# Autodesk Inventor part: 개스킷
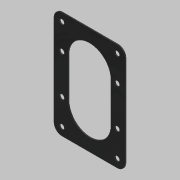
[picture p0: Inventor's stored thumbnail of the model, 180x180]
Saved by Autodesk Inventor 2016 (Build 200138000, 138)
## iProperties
Created: 2019-03
Part Number: 개스킷
Material: 고무
Document SubType Name: Modeling
Designer: mduedu
Density: 1 g/cm^3
Appearance: 고무 - 검은색 - 버전 1.1
Author: mduedu
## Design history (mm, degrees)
sketch "스케치1"
  geometry: L1 (-60, 40)-(60, 40); L2 (60, 40)-(60, -40); L3 (60, -40)-(-60, -40); L4 (-60, -40)-(-60, 40); L5 (-60, 40)-(60, -40); L6 (60, 40)-(-60, -40); 1 further point
  constraints: 12 end point, 2 midpoint, 2 parallel, 1 horizontal, 1 perpendicular
  dimensions: "d21" = 120 distance of L2.end L3.end; "d22" = 80 distance of L1.end L2.end
extrude "돌출1" new body sketch "스케치1" distance "d3" = 1; taper "d4" = 0 deg
fillet "모깎기1" dims "d5" = 9
sketch "스케치2" dims "d6" = 48
  geometry: L1 (-24, -22)-(24, -22); L2 (24, -22)-(24, 22); L3 (24, 22)-(-24, 22); L4 (-24, 22)-(-24, -22); L5 (-24, -22)-(24, 22); L6 (24, -22)-(-24, 22); 3 further points
  constraints: 12 end point, 4 midpoint, 2 horizontal alignment, 2 parallel, 1 horizontal, 1 perpendicular, 4 other
  dimensions: "d8" = 22 distance from line of L3 point (0, 0)
extrude "돌출2" cut sketch "스케치2" stored distance "d9" = 1; taper "d10" = 0 deg
sketch "스케치3"
  geometry: L1 (-24, -22)-(-24, 22) reference; L2 (24, 22)-(24, -22) reference; L3 (40, -51)-(40, 51) reference; L4 (31, 60)-(-31, 60) reference; L5 (-40, 51)-(-40, -51) reference; L6 (-31, -60)-(31, -60) reference; L7 (-31, 51)-(31, 51); L8 (31, 51)-(31, -51); L9 (31, -51)-(-31, -51); L10 (-31, -51)-(-31, 51); A1 r 24 centre (0, 22) between (24, 22) and (-24, 22) reference; A2 r 24 centre (0, -22) between (-24, -22) and (24, -22) reference; A3 r 9 centre (31, -51) between (31, -60) and (40, -51) reference; A4 r 9 centre (31, 51) between (40, 51) and (31, 60) reference; A5 r 9 centre (-31, 51) between (-31, 60) and (-40, 51) reference; A6 r 9 centre (-31, -51) between (-40, -51) and (-31, -60) reference; 9 further points
  constraints: 8 end point, 4 coincident, 4 horizontal alignment, 4 point on line, 2 parallel, 1 horizontal, 1 perpendicular
  dimensions: "d23" = 102 distance between parallel lines of L9 L7 (derived); "d24" = 29 distance from line of point (-31, 22) L7 (derived); "d25" = 29 distance from line of point (-31, -22) L9 (derived)
hole "구멍1" sketch "스케치3" at (-31, 51), (31, 51), (31, -51), (-31, -51), (-31, -22), (-31, 22), (31, 22), (31, -22) diameter "d14" = 5.5; stored, may be unused: countersink angle "d18" = 90 deg, drill point angle "d20" = 118 deg; dims "d15" = 6, "d16" = 4, "d17" = 2, "d19" = 8
node "솔리드1"
node "투영된 루프1"
